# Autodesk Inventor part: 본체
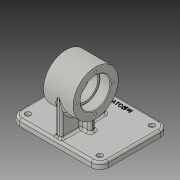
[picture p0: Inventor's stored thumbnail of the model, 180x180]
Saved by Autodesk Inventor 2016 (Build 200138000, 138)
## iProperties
Created: 2019-09
Part Number: 본체
Material: 일반
Document SubType Name: Modeling
Designer: Administrator
Density: 1 g/cm^3
Appearance: 기본값
Author: Administrator
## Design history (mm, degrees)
sketch "스케치1"
  geometry: L1 (-63, 49)-(63, 49); L2 (63, 49)-(63, -49); L3 (63, -49)-(-63, -49); L4 (-63, -49)-(-63, 49); L5 (-63, 49)-(63, -49); L6 (63, 49)-(-63, -49); 1 further point
  constraints: 12 end point, 2 midpoint, 2 parallel, 1 horizontal, 1 perpendicular
  dimensions: "d0" = 126 distance of L2.end L3.end; "d1" = 98 distance of L1.end L2.end
extrude "돌출1" new body sketch "스케치1" distance "d2" = 9; taper "d3" = 0 deg
fillet "모깎기1" dims "d4" = 12
fillet "모깎기2" dims "d5" = 3
sketch "스케치3"
  geometry: L1 (-51, 37)-(51, 37); L2 (51, 37)-(51, -37); L3 (51, -37)-(-51, -37); L4 (-51, -37)-(-51, 37); L5 (-51, 37)-(51, -37); L6 (51, 37)-(-51, -37); 1 further point
  constraints: 12 end point, 2 midpoint, 2 parallel, 1 horizontal, 1 perpendicular
  dimensions: "d12" = 102 distance of L2.end L3.end; "d13" = 74 distance of L1.end L2.end
hole "구멍1" sketch "스케치3" at (-51, -37), (51, -37), (51, 37), (-51, 37) diameter "d14" = 4.5; stored, may be unused: countersink angle "d18" = 90 deg, drill point angle "d20" = 118 deg; dims "d15" = 6, "d16" = 8, "d17" = 4.4, "d19" = 8
sketch "스케치4"
  geometry: L1 (-37, 0)-(37, 0) reference; L2 (-49, 0)-(-49, 6) reference; C1 r 32 at (-13, 59); 1 further point
  constraints: 1 centre point
  dimensions: "d21" = 32 radius of C1; "d22" = 59 distance from line of L1 C1.centre; "d23" = 36 distance from line of L2 C1.centre
sketch "스케치5"
  geometry: L1 (-4, 19)-(4, 19); L2 (4, 19)-(4, -45); L3 (4, -45)-(-4, -45); L4 (-4, -45)-(-4, 19); L5 (-4, 19)-(4, -45); L6 (4, 19)-(-4, -45); L7 (-17, -9)-(17, -9); L8 (17, -9)-(17, -17); L9 (17, -17)-(-17, -17); L10 (-17, -17)-(-17, -9); L11 (-17, -9)-(17, -17); L12 (17, -9)-(-17, -17); L13 (51, 49)-(-51, 49) reference; 3 further points
  constraints: 24 end point, 5 midpoint, 4 parallel, 2 horizontal, 2 perpendicular, 1 vertical alignment
  dimensions: "d24" = 8 distance of L2.end L3.end; "d25" = 64 distance of L1.end L2.end; "d26" = 34 distance of L8.end L9.end; "d27" = 8 distance of L7.end L8.end; "d28" = 62 distance from line of L13 point (0, -13)
extrude "돌출3" join sketch "스케치5" distance "d29" = 50; taper "d30" = 0 deg
extrude "돌출4" join sketch "스케치4" stored distance "d31" = 42; taper "d32" = 0 deg
fillet "모깎기3" dims "d33" = 3
fillet "모깎기4" dims "d34" = 3
hole "구멍2" diameter "d37" = 36; stored, may be unused: countersink angle "d41" = 90 deg, drill point angle "d43" = 118 deg; dims "d35" = 10, "d36" = 10, "d38" = 6, "d39" = 42, "d40" = 15, "d42" = 8
hole "구멍3" diameter "d46" = 36; stored, may be unused: countersink angle "d50" = 90 deg, drill point angle "d52" = 118 deg; dims "d44" = 10, "d45" = 10, "d47" = 6, "d48" = 42, "d49" = 15, "d51" = 8
fillet "모깎기5" dims "d53" = 0.3
chamfer "모따기1" distance "d54" = 1; stored, may be unused: second distance "d55" = 2, angle "d56" = 45 deg
sketch "스케치6"
  geometry: L1 (59, 50)-(59, -24) reference; L2 (53, -36)-(59, -36) reference; A1 r 26 centre (0, 0) between (-26, 0) and (0, -26); 3 further points
  constraints: 4 point on circle, 1 centre point
  dimensions: "d57" = 26 radius of A1; "d58" = 59 distance from line of L1 A1.centre; "d59" = 36 distance from line of L2 A1.centre
hole "구멍4" sketch "스케치6" at (-26, 0), (0, -26), (26, 0), (0, 26) diameter "d60" = 3.242; stored, may be unused: countersink angle "d64" = 90 deg, drill point angle "d66" = 118 deg; dims "d61" = 8, "d62" = 42, "d63" = 15, "d65" = 10
sketch "스케치7"
  geometry: L1 (63, -37)-(63, 37) reference; L2 (51, 49)-(-51, 49) reference; 2 further points
  constraints: 1 other
  dimensions: "d67" = 63 distance from line of L1 point (0, 39); "d68" = 10 distance from line of L2 point (0, 39)
feature "엠보싱1" sketch "스케치7" dims "d0" = 126, "d1" = 98, "d12" = 102, "d13" = 74, "d69" = 0.5, "d70" = 0
node "솔리드1"
mirror "대칭1"
